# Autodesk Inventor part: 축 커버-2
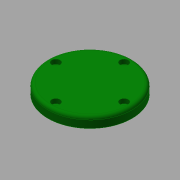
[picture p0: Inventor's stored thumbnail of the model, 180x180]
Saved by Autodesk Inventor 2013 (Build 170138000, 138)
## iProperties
Created: 2015-10
Part Number: 축 커버-2
Document SubType Name: Modeling
Designer: mdu
Density: 1 g/cm^3
Material: 강철, 연강
Author: mdu
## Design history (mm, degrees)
sketch "스케치1"
  geometry: C1 r 40 at (0, 0) reference; C2 r 26 at (0, 0) reference; 1 further point
  node "참조1"
  node "참조2"
extrude "돌출1" new body sketch "스케치1" distance "d0" = 10; taper "d1" = 0 deg
extrude "돌출2" join sketch "스케치1" distance "d2" = 3; taper "d3" = 0 deg
sketch "스케치2"
  geometry: C1 r 20 at (0, 0); 1 further point
  constraints: 1 centre point, 1 coincident
  dimensions: "d13" = 40 diameter of C1
extrude "돌출3" cut sketch "스케치2" distance "d14" = 3; taper "d15" = 0 deg
sketch "스케치3"
  geometry: C1 r 1.621 at (0, 32.5) reference; 1 further point
hole "구멍2" sketch "스케치3" at (0, 32.5) diameter "d16" = 4.5; stored, may be unused: countersink angle "d20" = 90 deg, drill point angle "d22" = 118 deg; dims "d17" = 6, "d18" = 8, "d19" = 4.4, "d21" = 8
fillet "모깎기1" dims "d26" = 3, "d27" = 0.3
chamfer "모따기1" distance "d28" = 1; stored, may be unused: second distance "d29" = 2, angle "d30" = 45 deg
node "솔리드1"
pattern_circular "원형 패턴1" dims angle "d24" = 360 deg
node "참조3"
